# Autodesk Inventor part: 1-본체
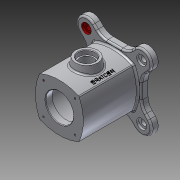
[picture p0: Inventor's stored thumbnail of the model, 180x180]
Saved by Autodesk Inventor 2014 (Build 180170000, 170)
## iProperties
Created: 2016-05
Part Number: 1-본체
Material: 알루미늄 6061
Document SubType Name: Modeling
Designer: Administrator
Density: 2.71 g/cm^3
Appearance: 알루미늄 - 평지
Mass: 1111.8 g
Surface Area: 864.256 cm^2
Volume: 410.258 cm^3
Author: Administrator
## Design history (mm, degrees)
sketch "스케치1"
  geometry: L1 (35.355, 35.355)-(-35.355, 35.355); L2 (-35.355, 35.355)-(-35.355, -35.355); L3 (-35.355, -35.355)-(35.355, -35.355); L4 (35.355, -35.355)-(35.355, 35.355); L5 (35.355, 35.355)-(-35.355, -35.355); L6 (-35.355, 35.355)-(35.355, -35.355); A1 r 85.579 centre (42.579, 0) between (-35.355, 35.355) and (-35.355, -35.355); A2 r 85.579 centre (0, -42.579) between (35.355, 35.355) and (-35.355, 35.355); A3 r 85.579 centre (-42.579, 0) between (35.355, -35.355) and (35.355, 35.355); A4 r 85.579 centre (0, 42.579) between (-35.355, -35.355) and (35.355, -35.355); 3 further points
  constraints: 12 end point, 8 point on circle, 4 centre point, 3 equal radius, 3 midpoint, 2 parallel, 1 coincident, 1 horizontal, 1 perpendicular
  dimensions: "d1" = 100 distance of L2.end L1.start; "d2" = 100 distance of L1.end L3.end (derived); "d3" = 45 deg angle of L6 L1; "d4" = 86 dimension on A1 A3
extrude "돌출1" new body sketch "스케치1" stored distance "d5" = 98; taper "d6" = 0 deg
sketch "스케치2"
  geometry: L1 (49, 49)-(-49, 49); L2 (-49, 49)-(-49, -49); L3 (-49, -49)-(49, -49); L4 (49, -49)-(49, 49); L5 (49, 49)-(-49, -49); L6 (-49, 49)-(49, -49); L7 (23.544, -49)-(36.77, -62.225); L8 (49, -23.544)-(62.225, -36.77); L9 (-23.544, -49)-(-36.77, -62.225); L10 (-49, -23.544)-(-62.225, -36.77); L11 (-49, 23.544)-(-62.225, 36.77); L12 (-23.544, 49)-(-36.77, 62.225); L13 (23.544, 49)-(36.77, 62.225); L14 (49, 23.544)-(62.225, 36.77); A1 r 18 centre (-49.497, -49.497) between (-36.77, -62.225) and (-62.225, -36.77); A2 r 70 centre (0, 0) between (-49.497, 49.497) and (49.497, -49.497); A3 r 18 centre (49.497, -49.497) between (36.77, -62.225) and (62.225, -36.77); A4 r 18 centre (49.497, 49.497) between (36.77, 62.225) and (62.225, 36.77); A5 r 18 centre (-49.497, 49.497) between (-62.225, 36.77) and (-36.77, 62.225); 1 further point
  constraints: 28 end point, 12 point on line, 11 point on circle, 8 tangent, 6 equal length, 5 centre point, 4 parallel, 3 equal radius, 2 midpoint, 1 coincident, 1 horizontal, 1 perpendicular
  dimensions: "d7" = 98 distance of L1.start L1.end; "d8" = 45 deg angle of L3 L5; "d62" = 70 distance of point (0, 0) A1.centre; "d64" = 18 radius of A1; "d66" = 70 radius of A2; "d76" = 98.99495 distance of A2.end A1.centre (derived); "d77" = 98.99495 distance of A2.start A1.centre (derived)
extrude "돌출2" join sketch "스케치2" distance "d13" = 12; taper "d14" = 0 deg
node "작업 평면3"
sketch "스케치5"
  geometry: C1 r 20 at (0, 0); 1 further point
  constraints: 1 centre point, 1 coincident
  dimensions: "d21" = 40 diameter of C1
extrude "돌출3" join sketch "스케치5" stored distance "d22" = 12; taper "d23" = 10 deg
sketch "스케치8"
  geometry: 1 further point
hole "구멍1" sketch "스케치8" at (0, 0) diameter "d24" = 50; stored, may be unused: countersink angle "d28" = 90 deg, drill point angle "d30" = 118 deg; dims "d25" = 6, "d26" = 4, "d27" = 2, "d29" = 8
sketch "스케치9"
  geometry: L1 (-37, 35)-(49, 35); L2 (49, 35)-(49, 0); L3 (49, 0)-(-37, 0); L4 (-37, 0)-(-37, 35); L5 (-49, -25)-(-49, 25) reference; L6 (61, -23.544)-(61, 23.544) reference; 5 further points
  constraints: 8 end point, 2 parallel, 1 horizontal, 1 perpendicular, 1 point on line
  dimensions: "d33" = 12 distance between parallel lines of L5 L4; "d34" = 12 distance between parallel lines of L6 L2; "d35" = 70 diameter of L1 L3
revolve "회전1" sketch "스케치9" stored, may be unused: angle "d36" = 90 deg
sketch "스케치10"
  geometry: L1 (0, 0)-(-28.284, 28.284); L2 (0, -93.8)-(0, 93.8) reference
  constraints: 2 end point
  dimensions: "d38" = 40 distance of L1.start L1.end; "d39" = 45 deg angle of L2 L1
hole "구멍2" sketch "스케치10" at (-28.284, 28.284) diameter "d40" = 3.242; stored, may be unused: countersink angle "d44" = 90 deg, drill point angle "d46" = 118 deg; dims "d41" = 7, "d42" = 4, "d43" = 2, "d45" = 10
sketch "스케치11"
  geometry: L1 (0, 0)-(28.284, -28.284); L2 (0, 94.496)-(0, -94.496) reference
  constraints: 2 end point
  dimensions: "d50" = 45 deg angle of L2 L1; "d51" = 40 distance of L1.start L1.end
hole "구멍3" sketch "스케치11" at (28.284, -28.284) diameter "d52" = 3.242; stored, may be unused: countersink angle "d56" = 90 deg, drill point angle "d58" = 118 deg; dims "d53" = 7, "d54" = 4, "d55" = 2, "d57" = 10
hole "구멍4" diameter "d69" = 10; stored, may be unused: countersink angle "d73" = 90 deg, drill point angle "d75" = 118 deg; dims "d67" = 10, "d68" = 10, "d70" = 7, "d71" = 18, "d72" = 4, "d74" = 10
hole "구멍5" diameter "d86" = 25; stored, may be unused: countersink angle "d90" = 90 deg, drill point angle "d92" = 118 deg; dims "d84" = 10, "d85" = 10, "d87" = 7, "d88" = 30, "d89" = 8, "d91" = 10
fillet "모깎기2" dims "d93" = 3
fillet "모깎기3" dims "d94" = 25
fillet "모깎기4" dims "d95" = 3
chamfer "모따기1" distance "d96" = 1; stored, may be unused: second distance "d97" = 2, angle "d98" = 45 deg
node "작업 평면7"
sketch "스케치15"
  geometry: L1 (-34.285, -49)-(34.285, -49) reference; 2 further points
  constraints: 1 other
  dimensions: "d107" = 29 distance of point (29, 0) point (0, 0); "d108" = 49 distance from line of L1 point (29, 0)
feature "엠보싱3" sketch "스케치15" dims "d1" = 100, "d2" = 100 (derived), "d3" = 45 deg, "d4" = 86, "d109" = 0.5, "d110" = 0
node "솔리드1"
pattern_circular "원형 패턴1" dims angle "d48" = 360 deg
pattern_circular "원형 패턴2" dims angle "d60" = 360 deg
pattern_linear "직사각형 패턴1" dims "d80" = 98.99495 (= d76), "d83" = 98.99495 (= d77)
other parameters: "d20" = 55
